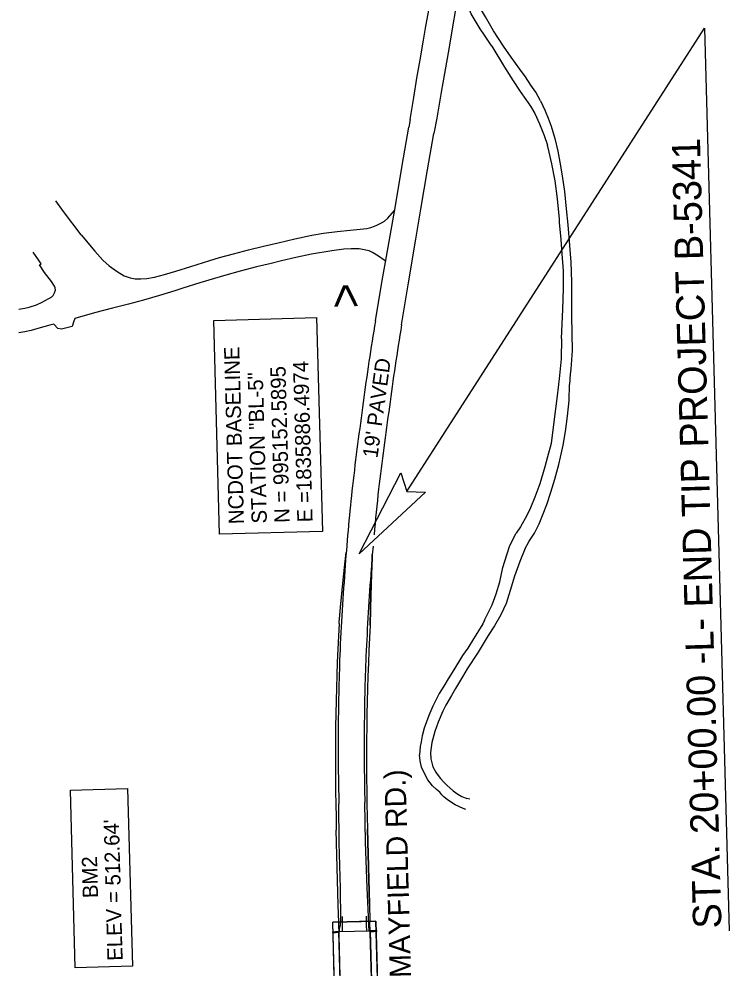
# Model space of a CAD drawing. Extents: x 1835096 to 1837089, y 993071 to 995976.
# Drawn here: x 1835647 to 1836148, y 994665 to 995335 of the extents above; entities that cross this region are included whole.
import ezdxf

# ---------------------------------------------------------------- set-up
doc = ezdxf.new("R2010")
doc.units = 0
for name, color, linetype in [('Default', 7, 'Continuous'), ('Exist Roads EOP', 7, 'Continuous'), ('Exist Roads EOP Other', 7, 'Continuous'), ('Exist Roads EOP Text', 7, 'Continuous'), ('Exist Roads EOT', 7, 'Continuous'), ('Exist Roads Soil', 7, 'Continuous'), ('Exist Structure Major Bridge WW', 7, 'Continuous'), ('Exist Structure Major Deck Tunnel Box Culvert', 7, 'Continuous'), ('Old_Level_57', 7, 'Continuous'), ('Prop EOT', 7, 'Continuous'), ('Prop Roadway Bridge', 7, 'Continuous'), ('Prop Shade Heavy', 7, 'Continuous'), ('Prop Shade Light', 7, 'Continuous'), ('Prop Terminator CELL', 7, 'Continuous'), ('Proposed Right of Way Monument PSD Text', 7, 'Continuous')]:
    doc.layers.add(name, color=color, linetype=linetype)

msp = doc.modelspace()

# ---------------------------------------------------------------- linework, layer by layer
at = {"layer": 'Default'}
for p, q in [((1835920.49, 995000.96), (1836130.59, 995328.02)), ((1836130.59, 995328.02), (1836147.98, 994690.98))]:
    msp.add_line(p, q, dxfattribs=at)
for points in [[(1835788.39, 994970.9), (1835784.27, 995121.77), (1835856.82, 995123.75), (1835860.94, 994972.88)], [(1835686.52, 994664.9), (1835683.1, 994790.22), (1835723.4, 994791.32), (1835726.83, 994666)]]:
    msp.add_lwpolyline(points, close=True, dxfattribs=at)
at = {"layer": 'Exist Roads EOP'}
for p, q in [((1835922.87, 995263.56), (1835922.07, 995258.06)), ((1835941.72, 995264.4), (1835939.54, 995253.73))]:
    msp.add_line(p, q, dxfattribs=at)
for points in [[(1835922.87, 995263.56), (1835925.4, 995279), (1835927.7, 995292.74), (1835929.87, 995305.65), (1835932.39, 995319.64), (1835934.04, 995329.4), (1835936.96, 995345.75), (1835939.27, 995359.3), (1835941.92, 995374.3), (1835944.27, 995388.09), (1835946.78, 995403.64), (1835949.77, 995422.09)], [(1835956.9, 995353.11), (1835954.9, 995341.17), (1835952.88, 995329.06), (1835950.46, 995314.51), (1835947.2, 995296.06), (1835944.86, 995282.93), (1835941.72, 995264.4)], [(1835898.44, 995121.39), (1835903.26, 995149.87), (1835905.47, 995162.78), (1835908.69, 995181.4), (1835912.46, 995202.67), (1835917.36, 995231.06), (1835922.07, 995258.06)], [(1835916.84, 995118.54), (1835921.6, 995146.82), (1835926.87, 995179.09), (1835930.38, 995200.29), (1835935.09, 995227.99), (1835939.54, 995253.73)], [(1835873.13, 994690.56), (1835873.03, 994692.69), (1835873.73, 994695.1), (1835873.88, 994698.89), (1835873.66, 994721), (1835872.9, 994753.05), (1835872.6, 994780.58)], [(1835893.95, 994691.09), (1835893.75, 994694.56), (1835893.39, 994701.11), (1835892.48, 994721.21), (1835891.45, 994753.39), (1835890.95, 994781.55)]]:
    msp.add_lwpolyline(points, dxfattribs=at)
for centre, major_axis, ratio, start_param, end_param in [((1837308.92, 994861.63), (96, -1471.29), 0.971064, 4.471991, 4.511501), ((1837653.51, 994848.79), (-695.18, -1652.23), 0.979281, 4.951697, 4.984334), ((1837192.63, 994942.7), (-342.09, -1896.88), 0.677504, 4.770526, 4.801345), ((1838782.69, 994796.91), (-746.07, -3717.17), 0.759534, 4.793443, 4.808919), ((1837641.28, 994819), (-1537.35, -877.61), 0.997858, 5.658085, 5.689962), ((1837572.45, 994795.61), (212.83, -1723.77), 0.968108, 4.473864, 4.492609), ((1837572.45, 994795.61), (212.83, -1723.77), 0.968108, 4.497221, 4.506477), ((1838842.42, 994787.42), (-752.59, -3006.2), 0.956853, 4.895233, 4.915759), ((1837429.91, 994784.38), (116.62, -1684.65), 0.91143, 4.55327, 4.589871), ((1838584.28, 994771.59), (509.65, -2735.87), 0.973767, 4.491951, 4.511482), ((1836976.28, 994806.52), (81.82, -1222.75), 0.885465, 4.589286, 4.632806), ((1837531.35, 994801.4), (258.34, -1718.06), 0.954025, 4.552705, 4.581901), ((1837262.48, 994826.14), (-424.13, -1316.45), 0.991177, 5.017601, 5.053758)]:
    msp.add_ellipse(centre, major_axis=major_axis, ratio=ratio, start_param=start_param, end_param=end_param, dxfattribs=at)
at = {"layer": 'Exist Roads EOP Other'}
for points in [[(1835690.67, 995182.18), (1835678.31, 995198.58), (1835672.9, 995206.15)], [(1835819.33, 995174.18), (1835829.68, 995176.52), (1835841.56, 995179.36), (1835853.6, 995181.85), (1835861.65, 995183.31), (1835871.44, 995184.54), (1835880.53, 995185.45), (1835889.94, 995186.34), (1835892.29, 995186.72), (1835895.04, 995187.36), (1835897.64, 995188.28), (1835899.46, 995188.99), (1835902.73, 995190.63), (1835904.84, 995191.91), (1835907.15, 995193.88), (1835911.76, 995199.28)], [(1835690.67, 995182.18), (1835700.42, 995170.58), (1835705.93, 995164.35), (1835710.53, 995160.33), (1835716.02, 995156.33), (1835721.13, 995153.27), (1835725.2, 995151.83), (1835728.72, 995151.2), (1835732.84, 995151.09), (1835737.09, 995151.36), (1835742.36, 995152.17), (1835749.49, 995154.12), (1835757.46, 995156.56), (1835768.06, 995159.83), (1835781.59, 995164.02), (1835788.29, 995166.07), (1835798.16, 995168.85), (1835808.87, 995171.66), (1835819.33, 995174.18)], [(1835905.62, 995163.64), (1835904.52, 995164.36), (1835900.63, 995167.02), (1835896.44, 995169.78), (1835894.03, 995170.88), (1835886.93, 995172.2), (1835881.28, 995172.32), (1835876.02, 995171.99), (1835867.72, 995170.88), (1835853.24, 995168.53), (1835842.27, 995166.21), (1835832.05, 995163.81), (1835824.82, 995162), (1835814.49, 995159.55), (1835803.01, 995156.59), (1835792.88, 995153.78), (1835784.72, 995151.28), (1835774.48, 995148.24), (1835762.55, 995144.5), (1835756.7, 995142.63), (1835745.9, 995139.35), (1835734.6, 995136.06), (1835724.08, 995133.27), (1835712.9, 995130.4), (1835700.15, 995127.07), (1835686.1, 995123.04), (1835685.2, 995120.63), (1835684.35, 995117.45), (1835676.81, 995115.54), (1835674.23, 995116.13), (1835671.37, 995119.03), (1835668.61, 995118.43), (1835660.08, 995116.04), (1835655.39, 995114.75), (1835650.83, 995113.71), (1835646.78, 995112.92)], [(1835661.38, 995160.87), (1835662.56, 995161.73), (1835660.63, 995164.57), (1835656.8, 995170.03)], [(1835646.79, 995129.76), (1835650.98, 995130.38), (1835654.05, 995131.13), (1835659.14, 995132.76), (1835663.21, 995134.65), (1835670, 995138.39), (1835670.93, 995139.28), (1835671.9, 995141.11), (1835672.48, 995143.21), (1835672.41, 995144.67), (1835671.96, 995145.97), (1835669.71, 995149.21), (1835664.79, 995155.52), (1835661.38, 995160.87)]]:
    msp.add_lwpolyline(points, dxfattribs=at)
at = {"layer": 'Exist Roads EOT'}
for points in [[(1835875.05, 994690.63), (1835875.07, 994692.53), (1835875.05, 994701.02)], [(1835892.29, 994691.05), (1835892.18, 994694.5), (1835892.04, 994701.31)]]:
    msp.add_lwpolyline(points, dxfattribs=at)
at = {"layer": 'Exist Roads Soil'}
for points in [[(1835988.73, 995315.3), (1835981.67, 995326.06), (1835976.12, 995335.97), (1835970.78, 995344.93), (1835966.99, 995351.41), (1835964.27, 995356.06), (1835960.83, 995360.95), (1835959.55, 995362.82), (1835958.89, 995364.57)], [(1835980.46, 995315.38), (1835975.38, 995322.97), (1835972.4, 995327.65), (1835969.4, 995332.23), (1835965.86, 995338.2), (1835963.83, 995343.42), (1835961.52, 995347.97)], [(1835980.46, 995315.38), (1835989.44, 995300.51), (1835995.64, 995290.8), (1836000.53, 995283.32), (1836004.49, 995277.74), (1836007.89, 995272.99), (1836010.94, 995267.71), (1836014.29, 995260.44), (1836017.52, 995252.38), (1836019.84, 995245.37)], [(1836015.01, 995276.66), (1836011.54, 995282.83), (1836008.02, 995287.76), (1836004.37, 995293.57), (1836000.24, 995299.02), (1835994.25, 995307.46), (1835988.73, 995315.3)], [(1836015.01, 995276.66), (1836018.18, 995269.74), (1836020.23, 995264.57), (1836022.49, 995258.84), (1836024.92, 995250.1), (1836027.2, 995241.16), (1836028.66, 995233.47), (1836030.17, 995223.85), (1836031.84, 995212.76), (1836033.14, 995200.5), (1836034.12, 995189.21), (1836035.48, 995174.61), (1836036.21, 995162.77), (1836036.82, 995148.96), (1836036.79, 995138.42), (1836036.91, 995124.89), (1836037.12, 995112.51), (1836037.21, 995100.52), (1836036.26, 995087.44), (1836035.97, 995083.74)], [(1836028.24, 995193.32), (1836026.89, 995207.66), (1836025.22, 995220.35), (1836022.87, 995232.16), (1836021.1, 995240.49), (1836019.84, 995245.37)], [(1836029.69, 995108.96), (1836030.65, 995129.42), (1836031.17, 995144.38), (1836031.13, 995156.76), (1836030.3, 995168.74), (1836029.52, 995178.86), (1836028.4, 995190.9), (1836028.24, 995193.32)], [(1836029.69, 995108.96), (1836029.5, 995094.61), (1836028.08, 995080.5), (1836027.6, 995076.66)], [(1836035.97, 995083.71), (1836035.4, 995076.59)], [(1836027.59, 995076.58), (1836026.34, 995066.63), (1836024.3, 995050.24), (1836022.39, 995034.91), (1836019.95, 995025.37), (1836017.9, 995018.4), (1836014.54, 995006.35), (1836010.86, 994997.04), (1836007.97, 994989.53), (1836005.32, 994984.01), (1836000.87, 994976.05), (1835997.67, 994971.56)], [(1836022.19, 995000.48), (1836025.02, 995009.8), (1836027.78, 995020.02), (1836029.13, 995025.3), (1836031.02, 995033.79), (1836032.53, 995043.25), (1836033.96, 995054.23), (1836035.07, 995065.15), (1836035.4, 995076.59)], [(1836003.75, 994960.36), (1836006.87, 994965.98), (1836010.6, 994971.66), (1836013.95, 994978.17), (1836016.79, 994985.16), (1836019.34, 994991.74), (1836022.19, 995000.48)], [(1835975.5, 994910.2), (1835980.8, 994921.06), (1835983.63, 994928.69), (1835986.09, 994937.19), (1835988.42, 994947.28), (1835991.05, 994956.21), (1835993.26, 994962.85), (1835997.67, 994971.56)], [(1836003.75, 994960.36), (1836000.33, 994951.49), (1835996.62, 994941.17), (1835993.45, 994931.09), (1835990.67, 994922.03), (1835986.81, 994914.03), (1835982.44, 994906.31)], [(1835975.5, 994910.2), (1835974.14, 994907.62), (1835971.07, 994902.58), (1835967.53, 994897.09), (1835963.52, 994890.48), (1835959.92, 994885.22), (1835953.81, 994875.11)], [(1835982.44, 994906.31), (1835977.9, 994899.36), (1835970.8, 994887.69), (1835963.26, 994875.74)], [(1835953.81, 994875.11), (1835949.85, 994868.76), (1835946.7, 994863.56), (1835943.4, 994858.36), (1835941.08, 994853.84), (1835938.97, 994849.49), (1835936.06, 994842.93), (1835932.85, 994833.98), (1835931.39, 994828.53), (1835930.6, 994824.3), (1835929.92, 994821.04), (1835929.45, 994815.04)], [(1835963.26, 994875.74), (1835959.83, 994870.19), (1835954.91, 994862.01), (1835952.1, 994856.92), (1835948.15, 994850.09), (1835945.98, 994846.04), (1835942.76, 994838.32), (1835940.44, 994831.66), (1835938.27, 994823.76), (1835937.23, 994816.88), (1835937.41, 994812.24), (1835938.89, 994806.79), (1835940.96, 994802.84), (1835941.99, 994801.42)], [(1835943.92, 994788.71), (1835941.52, 994790.7), (1835938.68, 994793.28), (1835935.37, 994797.55), (1835932.87, 994802.35), (1835931.02, 994806.49), (1835929.86, 994810.92), (1835929.45, 994815.04)], [(1835941.99, 994801.42), (1835944.22, 994798.45), (1835946.64, 994795.92), (1835948.8, 994793.82), (1835953.18, 994789.68), (1835956.62, 994787.31), (1835959.28, 994785.67), (1835962.85, 994784.4)], [(1835962.28, 994776.67), (1835960.28, 994777.3), (1835954.64, 994779.94), (1835949.36, 994783.32), (1835946.77, 994785.62), (1835945.36, 994786.93), (1835943.92, 994788.71)], [(1835965.11, 994783.74), (1835962.85, 994784.4)]]:
    msp.add_lwpolyline(points, dxfattribs=at)
at = {"layer": 'Exist Structure Major Bridge WW'}
for points in [[(1835872.64, 994689.66), (1835870.25, 994689.58), (1835868.26, 994689.5), (1835868.22, 994690.3), (1835870.19, 994690.37), (1835872.62, 994690.46)], [(1835894.78, 994691.06), (1835897.19, 994691.1), (1835899.23, 994691.14), (1835899.25, 994690.34), (1835897.27, 994690.3), (1835894.8, 994690.26)]]:
    msp.add_lwpolyline(points, dxfattribs=at)
at = {"layer": 'Exist Structure Major Deck Tunnel Box Culvert'}
for points in [[(1835872.62, 994690.49), (1835894.78, 994691.04)], [(1835877.36, 994515.29), (1835872.62, 994690.49)], [(1835894.78, 994691.04), (1835899.42, 994515.82)]]:
    msp.add_lwpolyline(points, dxfattribs=at)
at = {"layer": 'Prop EOT'}
for p, q in [((1835872.2, 994709.13), (1835870.79, 994762.02)), ((1835894.2, 994709.72), (1835892.78, 994762.61))]:
    msp.add_line(p, q, dxfattribs=at)
for radius in [1821, 1799]:
    msp.add_arc((1837691.14, 994810.76), radius, 176.94086, 181.53384, dxfattribs=at)
for points in [[(1835872.73, 994907.94), (1835872.79, 994908.62), (1835872.85, 994909.3), (1835872.91, 994909.98), (1835872.97, 994910.65), (1835873.03, 994911.33), (1835873.09, 994912.01), (1835873.15, 994912.69), (1835873.21, 994913.36), (1835873.27, 994914.04), (1835873.33, 994914.72), (1835873.39, 994915.39), (1835873.45, 994916.07), (1835873.51, 994916.75), (1835873.57, 994917.43), (1835873.64, 994918.1), (1835873.7, 994918.78), (1835873.76, 994919.46), (1835873.82, 994920.13), (1835873.89, 994920.81), (1835873.95, 994921.49), (1835874.01, 994922.17), (1835874.08, 994922.84), (1835874.14, 994923.52), (1835874.21, 994924.2), (1835874.27, 994924.87), (1835874.33, 994925.55), (1835874.4, 994926.23), (1835874.46, 994926.9), (1835874.53, 994927.58), (1835874.6, 994928.26), (1835874.66, 994928.93), (1835874.73, 994929.61), (1835874.8, 994930.29), (1835874.86, 994930.96), (1835874.93, 994931.64), (1835875, 994932.32), (1835875.06, 994932.99), (1835875.13, 994933.67), (1835875.2, 994934.35), (1835875.27, 994935.02), (1835875.34, 994935.7), (1835875.41, 994936.38), (1835875.48, 994937.05), (1835875.54, 994937.73), (1835875.61, 994938.4), (1835875.68, 994939.08), (1835875.75, 994939.76), (1835875.82, 994940.43), (1835875.9, 994941.11), (1835875.97, 994941.78), (1835876.04, 994942.46), (1835876.11, 994943.14), (1835876.18, 994943.81), (1835876.25, 994944.49), (1835876.32, 994945.16), (1835876.4, 994945.84), (1835876.47, 994946.52), (1835876.54, 994947.19), (1835876.62, 994947.87), (1835876.69, 994948.54), (1835876.76, 994949.22), (1835876.84, 994949.89), (1835876.91, 994950.57), (1835876.99, 994951.25), (1835877.06, 994951.92), (1835877.13, 994952.6), (1835877.21, 994953.27), (1835877.29, 994953.95), (1835877.36, 994954.62), (1835877.44, 994955.3), (1835877.51, 994955.97), (1835877.59, 994956.65), (1835877.74, 994958)], [(1835894.7, 994906.77), (1835894.71, 994907.44), (1835894.72, 994908.11), (1835894.73, 994908.78), (1835894.75, 994909.46), (1835894.76, 994910.13), (1835894.77, 994910.8), (1835894.78, 994911.47), (1835894.79, 994912.14), (1835894.81, 994912.82), (1835894.82, 994913.49), (1835894.83, 994914.16), (1835894.85, 994914.83), (1835894.86, 994915.5), (1835894.88, 994916.18), (1835894.89, 994916.85), (1835894.91, 994917.52), (1835894.92, 994918.19), (1835894.94, 994918.86), (1835894.95, 994919.54), (1835894.97, 994920.21), (1835894.98, 994920.88), (1835895, 994921.55), (1835895.02, 994922.22), (1835895.03, 994922.9), (1835895.05, 994923.57), (1835895.07, 994924.24), (1835895.09, 994924.91), (1835895.1, 994925.58), (1835895.12, 994926.26), (1835895.14, 994926.93), (1835895.16, 994927.6), (1835895.18, 994928.27), (1835895.2, 994928.94), (1835895.22, 994929.62), (1835895.24, 994930.29), (1835895.26, 994930.96), (1835895.28, 994931.63), (1835895.3, 994932.31), (1835895.32, 994932.98), (1835895.34, 994933.65), (1835895.36, 994934.32), (1835895.38, 994934.99), (1835895.4, 994935.67), (1835895.42, 994936.34), (1835895.45, 994937.01), (1835895.47, 994937.68), (1835895.49, 994938.35), (1835895.51, 994939.03), (1835895.54, 994939.7), (1835895.56, 994940.37), (1835895.58, 994941.04), (1835895.61, 994941.71), (1835895.63, 994942.39), (1835895.66, 994943.06), (1835895.68, 994943.73), (1835895.71, 994944.4), (1835895.73, 994945.07), (1835895.76, 994945.75), (1835895.78, 994946.42), (1835895.81, 994947.09), (1835895.83, 994947.76), (1835895.86, 994948.44), (1835895.89, 994949.11), (1835895.91, 994949.78), (1835895.94, 994950.45), (1835895.97, 994951.12), (1835896, 994951.8), (1835896.02, 994952.47), (1835896.05, 994953.14), (1835896.08, 994953.81), (1835896.11, 994954.48), (1835896.14, 994955.16), (1835896.2, 994956.5)]]:
    msp.add_spline(points, degree=3, dxfattribs=at)
at = {"layer": 'Prop Roadway Bridge'}
for p, q in [((1835898.77, 994697.84), (1835868.28, 994697.02)), ((1835873.36, 994507.09), (1835868.28, 994697.02)), ((1835877.61, 994507.2), (1835872.53, 994697.14)), ((1835899.6, 994507.79), (1835894.52, 994697.72)), ((1835903.85, 994507.91), (1835898.77, 994697.84))]:
    msp.add_line(p, q, dxfattribs=at)
at = {"layer": 'Prop Shade Heavy'}
msp.add_lwpolyline([(1835873.36, 994507.09), (1835868.28, 994697.02), (1835898.77, 994697.84), (1835903.85, 994507.91)], close=True, dxfattribs=at)
at = {"layer": 'Prop Shade Light'}
for p, q in [((1835872.2, 994709.13), (1835870.79, 994762.02)), ((1835892.78, 994762.61), (1835894.2, 994709.72)), ((1835872.53, 994697.14), (1835872.2, 994709.13)), ((1835894.2, 994709.72), (1835894.52, 994697.72)), ((1835894.52, 994697.72), (1835872.53, 994697.14))]:
    msp.add_line(p, q, dxfattribs=at)
for radius in [1821, 1799]:
    msp.add_arc((1837691.14, 994810.76), radius, 176.94086, 181.53384, dxfattribs=at)
for points in [[(1835872.73, 994907.94), (1835872.79, 994908.62), (1835872.85, 994909.3), (1835872.91, 994909.98), (1835872.97, 994910.65), (1835873.03, 994911.33), (1835873.09, 994912.01), (1835873.15, 994912.69), (1835873.21, 994913.36), (1835873.27, 994914.04), (1835873.33, 994914.72), (1835873.39, 994915.39), (1835873.45, 994916.07), (1835873.51, 994916.75), (1835873.57, 994917.43), (1835873.64, 994918.1), (1835873.7, 994918.78), (1835873.76, 994919.46), (1835873.82, 994920.13), (1835873.89, 994920.81), (1835873.95, 994921.49), (1835874.01, 994922.17), (1835874.08, 994922.84), (1835874.14, 994923.52), (1835874.21, 994924.2), (1835874.27, 994924.87), (1835874.33, 994925.55), (1835874.4, 994926.23), (1835874.46, 994926.9), (1835874.53, 994927.58), (1835874.6, 994928.26), (1835874.66, 994928.93), (1835874.73, 994929.61), (1835874.8, 994930.29), (1835874.86, 994930.96), (1835874.93, 994931.64), (1835875, 994932.32), (1835875.06, 994932.99), (1835875.13, 994933.67), (1835875.2, 994934.35), (1835875.27, 994935.02), (1835875.34, 994935.7), (1835875.41, 994936.38), (1835875.48, 994937.05), (1835875.54, 994937.73), (1835875.61, 994938.4), (1835875.68, 994939.08), (1835875.75, 994939.76), (1835875.82, 994940.43), (1835875.9, 994941.11), (1835875.97, 994941.78), (1835876.04, 994942.46), (1835876.11, 994943.14), (1835876.18, 994943.81), (1835876.25, 994944.49), (1835876.32, 994945.16), (1835876.4, 994945.84), (1835876.47, 994946.52), (1835876.54, 994947.19), (1835876.62, 994947.87), (1835876.69, 994948.54), (1835876.76, 994949.22), (1835876.84, 994949.89), (1835876.91, 994950.57), (1835876.99, 994951.25), (1835877.06, 994951.92), (1835877.13, 994952.6), (1835877.21, 994953.27), (1835877.29, 994953.95), (1835877.36, 994954.62), (1835877.44, 994955.3), (1835877.51, 994955.97), (1835877.59, 994956.65), (1835877.74, 994958)], [(1835896.2, 994956.5), (1835896.14, 994955.16), (1835896.11, 994954.48), (1835896.08, 994953.81), (1835896.05, 994953.14), (1835896.02, 994952.47), (1835896, 994951.8), (1835895.97, 994951.12), (1835895.94, 994950.45), (1835895.91, 994949.78), (1835895.89, 994949.11), (1835895.86, 994948.44), (1835895.83, 994947.76), (1835895.81, 994947.09), (1835895.78, 994946.42), (1835895.76, 994945.75), (1835895.73, 994945.07), (1835895.71, 994944.4), (1835895.68, 994943.73), (1835895.66, 994943.06), (1835895.63, 994942.39), (1835895.61, 994941.71), (1835895.58, 994941.04), (1835895.56, 994940.37), (1835895.54, 994939.7), (1835895.51, 994939.03), (1835895.49, 994938.35), (1835895.47, 994937.68), (1835895.45, 994937.01), (1835895.42, 994936.34), (1835895.4, 994935.67), (1835895.38, 994934.99), (1835895.36, 994934.32), (1835895.34, 994933.65), (1835895.32, 994932.98), (1835895.3, 994932.31), (1835895.28, 994931.63), (1835895.26, 994930.96), (1835895.24, 994930.29), (1835895.22, 994929.62), (1835895.2, 994928.94), (1835895.18, 994928.27), (1835895.16, 994927.6), (1835895.14, 994926.93), (1835895.12, 994926.26), (1835895.1, 994925.58), (1835895.09, 994924.91), (1835895.07, 994924.24), (1835895.05, 994923.57), (1835895.03, 994922.9), (1835895.02, 994922.22), (1835895, 994921.55), (1835894.98, 994920.88), (1835894.97, 994920.21), (1835894.95, 994919.54), (1835894.94, 994918.86), (1835894.92, 994918.19), (1835894.91, 994917.52), (1835894.89, 994916.85), (1835894.88, 994916.18), (1835894.86, 994915.5), (1835894.85, 994914.83), (1835894.83, 994914.16), (1835894.82, 994913.49), (1835894.81, 994912.82), (1835894.79, 994912.14), (1835894.78, 994911.47), (1835894.77, 994910.8), (1835894.76, 994910.13), (1835894.75, 994909.46), (1835894.73, 994908.78), (1835894.72, 994908.11), (1835894.71, 994907.44), (1835894.7, 994906.77)]]:
    msp.add_spline(points, degree=3, dxfattribs=at)
at = {"layer": 'Prop Terminator CELL'}
msp.add_lwpolyline([(1835933.78, 995000.52), (1835887.03, 994956.92), (1835916.44, 995014.14), (1835920.49, 995000.96)], close=True, dxfattribs=at)

# ---------------------------------------------------------------- texts
at = {"layer": 'Default'}
for s, height, p in [('STA. 20+00.00 -L- END TIP PROJECT B-5341', 20, (1836142.7, 994692.79)), ('-L- SR 1767 (MAYFIELD RD.)', 15, (1835926.86, 994537.6))]:
    msp.add_text(s, height=height, rotation=91.56434, dxfattribs=at).set_placement(p)
at = {"layer": 'Exist Roads EOP Text'}
msp.add_text("19' PAVED", height=10.648, rotation=82.29899, dxfattribs=at).set_placement((1835899.82, 995024.23))
at = {"layer": 'Old_Level_57'}
msp.add_text('>', height=22.96, rotation=91.57854, dxfattribs=at).set_placement((1835888.7, 995130.42))
at = {"layer": 'Proposed Right of Way Monument PSD Text'}
for s, p in [('NCDOT BASELINE', (1835805.67, 994978.09)), ('E =1835886.4974', (1835854.04, 994979.41)), ('STATION "BL-5"', (1835821.8, 994978.53)), ('N = 995152.5895', (1835837.92, 994978.97)), ("ELEV = 512.64'", (1835720, 994669.92)), ('BM2', (1835702.65, 994714.16))]:
    msp.add_text(s, height=10.752, rotation=91.56434, dxfattribs=at).set_placement(p)

doc.saveas('drawing.dxf')
